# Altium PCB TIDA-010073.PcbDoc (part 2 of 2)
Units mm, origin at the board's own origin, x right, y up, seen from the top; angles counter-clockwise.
Board outline 68.14 x 25.33 mm, 2 copper layers (Top Layer, Bottom Layer), stack 1.575 mm thick; 47 components, 34 nets, 125 pads, 64 vias.
Unrouted connection lines stored in the file: 4.
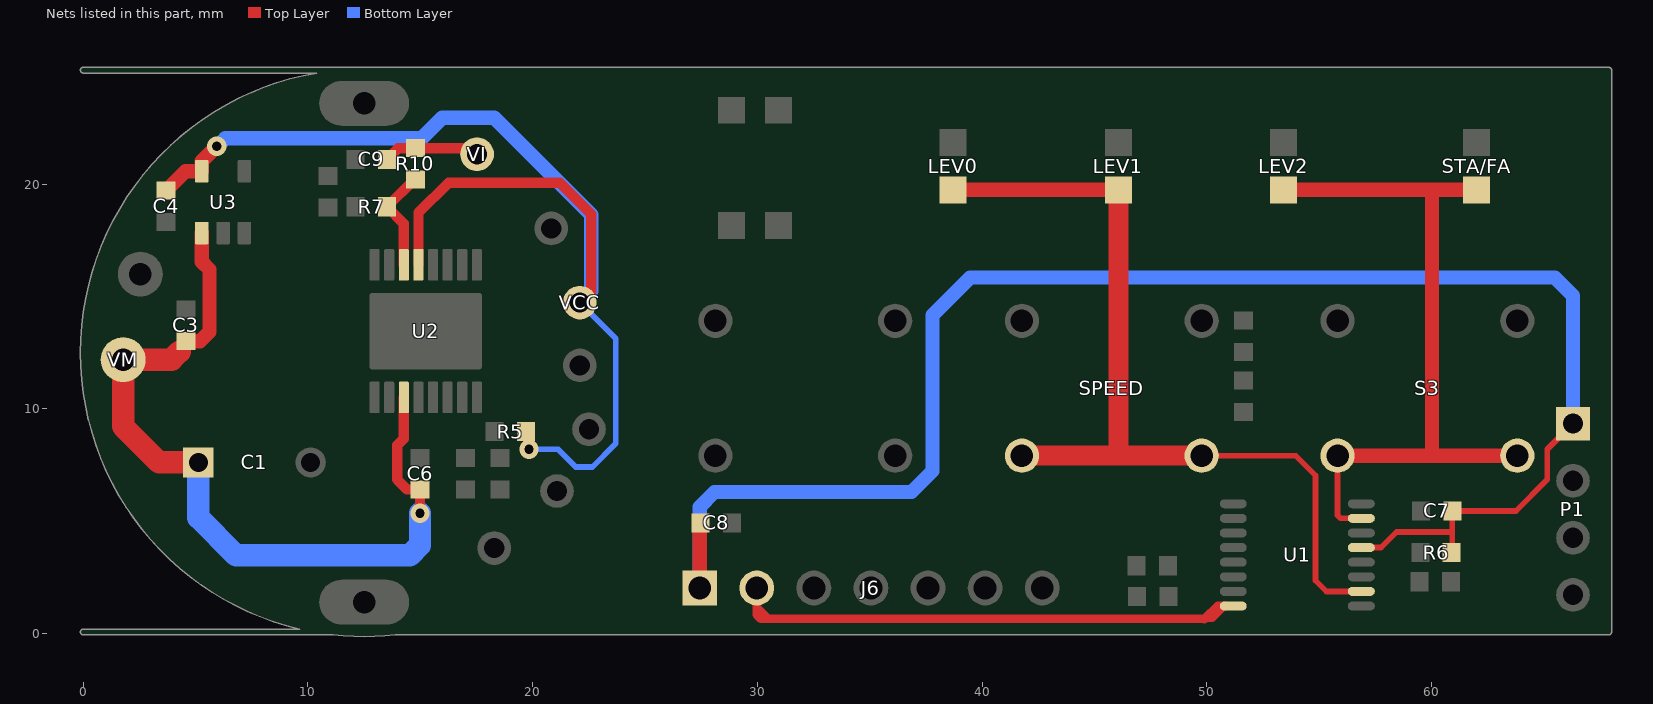
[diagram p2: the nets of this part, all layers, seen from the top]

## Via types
v1: diameter 0.508, hole 0.381, Top Layer to Bottom Layer, 28 vias
v2: diameter 0.864, hole 0.406, Top Layer to Bottom Layer, 19 vias
v3: diameter 0.5, hole 0.2, Top Layer to Bottom Layer, tented both sides, 12 vias
v4: diameter 0.5, hole 0.2, Top Layer to Bottom Layer, 3 vias
v5: diameter 0.508, hole 0.254, Top Layer to Bottom Layer, 2 vias

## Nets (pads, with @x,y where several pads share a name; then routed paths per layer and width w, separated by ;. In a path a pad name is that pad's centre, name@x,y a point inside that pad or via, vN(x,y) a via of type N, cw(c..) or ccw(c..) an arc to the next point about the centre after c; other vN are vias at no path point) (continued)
Seg1_MCU: LEV0.1 LEV1.1 SPEED.B SPEED.D U1.2 | length 39.5
  Top Layer w0.254: SPEED.D@49.771,7.922 53.952,7.922 54.839,7.036 54.839,2.362 55.321,1.88 U1.2@56.876,1.88
  Top Layer w0.635: LEV0.1@38.71,19.753 LEV1.1@46.063,19.753
  Top Layer w0.889: SPEED.B@41.771,7.922 46.076,7.922 ; LEV1.1@46.063,19.753 46.063,7.935 46.076,7.922 ; SPEED.D@49.771,7.922 46.076,7.922
Seg2_MCU: LEV2.1 S3.B S3.D STA/FA.1 U1.7 | length 32.2
  Top Layer w0.254: S3.B@55.817,7.922 55.817,5.27 55.957,5.13 U1.7@56.876,5.13
  Top Layer w0.635: LEV2.1@53.416,19.753 STA/FA.1@62.001,19.753 ; S3.B@55.817,7.922 60.02,7.922 ; 60.02,19.727 60.02,7.922 ; S3.D@63.817,7.922 60.02,7.922
V_IPROPI: R7.2 R10.1 U2.6 | length 4.7
  Top Layer w0.457: U2.6@14.265,16.412 14.265,18.25 R7.2@13.516,18.999 14.721,20.204 R10.1@14.783,20.204
V_IPROPI_Fil: C9.1 R10.2 VI.1 | length 4.3
  Top Layer w0.457: C9.1@13.513,21.107 14.01,21.604 R10.2@14.783,21.604 17.258,21.604 VI.1@17.526,21.336
V_IPROPI_MCU: J6.2 U1.16 | length 24.8
  Top Layer w0.254: J6.2@29.972,2.032 29.972,1.245 30.556,0.66 ; 49.886,0.635 50.256,0.635 50.851,1.23 U1.16@51.176,1.23
  Top Layer w0.381: 29.972,1.245 29.972,0.838 30.15,0.66 30.556,0.66 49.911,0.66 ; 49.886,0.635 49.911,0.66 ; U1.16@50.851,1.23 50.481,1.23 49.911,0.66
VCC: C4.1 R5.1 U2.5 U3.5 VCC.1 | length 54.1
  Top Layer w0.254: R5.1@19.699,8.992 19.699,8.342 v2(19.837,8.204)
  Top Layer w0.457: U2.5@14.915,16.412 14.915,18.725 16.256,20.066 21.212,20.066 22.606,18.672 22.606,15.24 VCC.1@22.098,14.732
  Top Layer w0.635: C4.1@3.683,19.713 4.547,20.577 U3.5@5.273,20.577 5.273,21.021 v2(5.944,21.692)
  Bottom Layer w0.254: v2(19.837,8.204) 21.133,8.204 21.92,7.417 22.657,7.417 23.698,8.458 23.698,13.132 VCC.1@22.098,14.732
  Bottom Layer w0.635: v2(5.944,21.692) 6.325,22.047 15.062,22.047 15.977,22.962 18.288,22.962 22.606,18.644 22.606,15.24 VCC.1@22.098,14.732
VCC1: C7.1 C8.1 J6.1 P1.1@66.294,9.347 R6.1 U1.5 | length 73.5
  Top Layer w0.254: U1.5@56.876,3.83 57.754,3.83 58.445,4.521 60.808,4.521 ; R6.1@60.898,3.607 60.923,3.632 C7.1@60.923,5.461 63.754,5.461 65.151,6.858 65.151,8.204 P1.1@66.294,9.347
  Top Layer w0.635: J6.1@27.432,2.032 27.432,4.891 C8.1@27.469,4.928
  Bottom Layer w0.635: J6.1@27.432,2.032 27.432,5.639 28.092,6.299 36.855,6.299 37.795,7.239 37.795,14.173 39.472,15.85 65.481,15.85 66.294,15.037 P1.1@66.294,9.347
VM: C1.1 C3.1 C6.1 U2.11 U3.1 VM.1 | length 36
  Top Layer w0.457: U2.11@14.265,10.512 14.265,8.677 13.97,8.382 13.97,6.858 14.416,6.412 C6.1@14.986,6.412 v2(14.986,5.359)
  Top Layer w0.635: C3.1@4.572,13.016 5.193,13.016 5.613,13.437 5.613,16.205 5.273,16.546 U3.1@5.273,17.827
  Top Layer w1: 4.293,12.548 3.937,12.192 VM.1@1.778,12.192 1.778,9.22 3.378,7.62 C1.1@5.12,7.62
  Bottom Layer w1: C1.1@5.12,7.62 5.12,5.167 6.807,3.48 14.529,3.48 14.986,3.937 v2(14.986,5.359)
pads on no net: LBL1.0 U1.8 U2.17@15.24,13.462 U3.3 U3.4

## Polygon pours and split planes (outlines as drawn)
GND1 on Bottom Layer "BOTTOM_LAYER_GND1_P000" (solid, remove dead copper, pour order 0): 25.885,25.076 25.885,0.076 67.885,0.076 67.885,25.076
GND on Bottom Layer "BOTTOM_LAYER_GND_P006" (solid, remove dead copper, pour order 6): 25.552,25.044 25.425,24.917 25.425,0.051 0.051,0.051 -0.025,0.127 -0.025,25.324
GND on Top Layer "TOP_LAYER_GND_P004" (solid, remove dead copper, pour order 4): -0.051,25.044 -0.025,25.019 -0.025,0.051 24.206,0.051 25.121,0.965 25.121,25.273 24.587,25.806
GND1 on Top Layer "TOP_LAYER_GND1_P002" (solid, remove dead copper, pour order 2): 25.885,25.07 25.885,0.076 67.885,0.076 67.885,25.076 67.841,25.121

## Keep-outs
Keep-Out Layer:
  circle w0.254: c12.5,12.5 r12.5
  lines w0.381: 25.885,25.07 25.885,0.076 25.961,0 67.809,0 67.885,0.076 67.885,25.076 67.841,25.121 25.93,25.121 25.885,25.076
  text ".Layer_Name" at 14.656,-21.806 h1.14

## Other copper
Top Layer:
  text ".Layer_Name" at 14.656,-21.806 h1.14
Bottom Layer:
  text ".Layer_Name" at 14.656,-21.806 h1.14

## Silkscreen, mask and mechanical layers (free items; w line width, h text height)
Top Overlay:
  text ".Layer_Name" at 14.656,-21.806 h1.14
Bottom Overlay:
  region: 12.421,6.198 4.801,6.198 4.801,3.658 12.421,3.658
  text "TIDA-010073.Rev.1" at 12.725,8.941 h1.14
  text "TIDA-010073.Rev.1" at 59.08,1.194 h1.14
  text ".Layer_Name" at 14.656,-21.806 h1.14
Top Paste:
  text ".Layer_Name" at 14.656,-21.806 h1.14
Bottom Paste:
  text ".Layer_Name" at 14.656,-21.806 h1.14
Top Solder:
  lines w0.381: 7.417,13.741 7.442,13.767 12.421,13.767 ; 7.696,15.85 9.068,14.478 12.294,14.478 ; 7.747,11.887 8.89,13.03 12.395,13.03 ; 8.052,10.693 9.601,12.243 12.446,12.243 ; 8.534,9.449 10.414,11.328 12.446,11.328
  text ".Layer_Name" at 14.656,-21.806 h1.14
  text ".Layer_Name" at 14.656,-21.806 h1.14
Bottom Solder:
  lines w0.381: 6.426,13.691 6.502,13.767 12.421,13.767 ; 6.985,18.952 7.133,18.952 11.608,14.478 12.294,14.478 ; 7.823,11.1 9.525,12.802 12.446,12.802 ; 8.534,9.449 11.048,11.962 12.69,11.962 ; 9.042,20.244 9.042,18.72 12.598,15.164 ; 10.414,8.992 12.573,11.151 12.598,11.151 ; 12.497,19.863 12.497,16.637 13.335,15.799 ; 13.52,7.638 13.52,11.278 13.52,11.575 ; 14.072,15.704 14.072,18.669 14.072,20.015 ; 14.511,7.662 14.529,7.68 14.529,11.405 ; 15.113,15.57 15.113,18.669 15.113,20.041 ; 15.443,11.557 15.443,7.68 15.461,7.662 ; 16.231,15.789 16.231,18.618 16.231,19.831 ; 16.383,7.874 16.383,11.506 ; 17.12,15.494 17.12,16.208 17.12,18.593 17.12,18.618 18.263,19.761 ; 17.399,7.918 17.399,11.532 ; 17.653,13.868 19.025,13.868 20.041,14.884 ; 17.678,15.011 18.44,15.011 19.761,16.332 ; 17.805,11.836 19.253,11.836 20.117,10.973 ; 17.805,12.802 19.761,12.802 20.422,13.462
  text ".Layer_Name" at 14.656,-21.806 h1.14
Drill Guide:
  text ".Layer_Name" at 14.656,-21.806 h1.14
M1 Board Outline:
  circle w0.254: c12.5,12.5 r12.5
  lines w0.254: 25.885,0.076 67.885,0.076 67.885,25.076 25.885,25.076 25.885,0.076
  text ".Layer_Name" at 14.656,-21.806 h1.14
M2 Board Dimensions:
  rectangle: 3.175,-10.16 12.7,-6.985
  rectangle: 0,-6.985 3.175,-3.81
  lines w0.178: 0,-6.985 25.4,-6.985 ; 3.175,-10.16 3.175,-3.81 ; 6.35,-10.16 6.35,-3.81 ; 12.7,-10.16 12.7,-3.81 ; 19.05,-10.16 19.05,-3.81 ; 0,-10.16 0,-3.81 25.4,-3.81 25.4,-10.16 0,-10.16
  text ".Layer_Name" at 14.656,-21.806 h1.14
M3 3D STEP Top:
  text ".Layer_Name" at 14.656,-21.806 h1.14
M4 3D STEP Bottom:
  text ".Layer_Name" at 14.656,-21.806 h1.14
M5 Assembly Top:
  lines w0.254: -7.417,-23.626 160.223,-23.626 ; -7.417,-18.462 160.274,-18.462 ; -7.417,-13.297 -7.417,-28.791 94.31,-28.791 160.274,-28.791 160.274,-13.297 -7.404,-13.297 -7.404,-28.791 32.614,-28.791 ; 55.194,-28.791 55.194,-13.297 ; 87.376,-18.462 87.376,-13.297 ; 108.712,-18.462 108.712,-13.297 ; 124.511,-28.956 124.511,-23.804
  text "COMPONENTS MARKED 'DNP' SHOULD NOT BE POPULATED." at 29.299,-8.09 h0.76
  text "ASSEMBLY VARIANT:" at 29.286,-11.024 h0.76
  text ".VariantName" at 55.601,-11.024 h0.76
  text "PCB VIEWED FROM TOP SIDE" at -5.804,-16.654 h1.14
  text "BOARD #:" at 57.099,-16.654 h1.14
  text ".PRJ_Number" at 70.955,-16.654 h1.14
  text "REV:" at 92.405,-16.654 h1.14
  text ".PCB_Rev" at 99.809,-16.654 h1.14
  text "SVN REV:" at 113.69,-16.654 h1.14
  text ".VersionControl_RevNumber" at 126.543,-16.654 h1.14
  text "TID #:" at 57.099,-21.819 h1.14
  text ".TID" at 70.955,-21.819 h1.14
  text "PLOT NAME =" at -5.804,-27.034 h1.14
  text ".plot_File_Name" at 14.656,-27.034 h1.14
  text "GENERATED    :" at 57.15,-27.034 h1.14
  text ".Print_Date" at 79.235,-27.034 h1.14
  text ".Print_Time" at 97.752,-27.034 h1.14
  text "TEXAS INSTRUMENTS" at 129.87,-27.034 h1.14
M6 Assembly Bottom:
  lines w0.254: -7.429,-18.474 160.261,-18.474 ; -7.379,-23.639 160.261,-23.639 ; 28.334,-28.969 28.334,-23.817 ; 44.133,-18.474 44.133,-13.31 ; 65.468,-18.474 65.468,-13.31 ; 97.65,-28.804 97.65,-13.31 ; 120.231,-28.804 160.249,-28.804 160.249,-13.31 -7.429,-13.31 -7.429,-28.804 58.534,-28.804 160.261,-28.804 160.261,-13.31
  text "COMPONENTS MARKED 'DNP' SHOULD NOT BE POPULATED." at 154.991,-8.077 h0.76
  text ".VariantName" at 128.473,-11.024 h0.76
  text "ASSEMBLY VARIANT:" at 154.864,-11.024 h0.76
  text ".VersionControl_RevNumber" at 26.302,-16.667 h1.14
  text "SVN REV:" at 39.154,-16.667 h1.14
  text ".PCB_Rev" at 53.035,-16.667 h1.14
  text "REV:" at 60.439,-16.667 h1.14
  text ".PRJ_Number" at 81.89,-16.667 h1.14
  text "BOARD #:" at 95.745,-16.667 h1.14
  text "PCB VIEWED FROM BOTTOM SIDE" at 158.648,-16.667 h1.14
  text ".TID" at 81.89,-21.831 h1.14
  text "TID #:" at 95.745,-21.831 h1.14
  text "TEXAS INSTRUMENTS" at 22.974,-27.047 h1.14
  text ".Print_Time" at 55.093,-27.047 h1.14
  text ".Print_Date" at 73.609,-27.047 h1.14
  text "GENERATED    :" at 95.694,-27.047 h1.14
  text ".plot_File_Name" at 138.189,-27.047 h1.14
  text "PLOT NAME =" at 158.648,-27.047 h1.14
M9 Title Sheet:
  drawing of 57 lines, arcs and shapes, not listed
  text "1" at 18.792,204.127 h1.14
  text "2" at 82.182,204.127 h1.14
  text "3" at 145.411,204.127 h1.14
  text "4" at 209.08,204.127 h1.14
  text "5" at 272.555,204.127 h1.14
  text "6" at 336.182,204.127 h1.14
  text "A" at -10.579,175.095 h1.14
  text "A" at 365.341,175.095 h1.14
  text "B" at -10.579,114.643 h1.14
  text "B" at 365.341,114.643 h1.14
  text "C" at -10.579,54.318 h1.14
  text "C" at 365.341,54.318 h1.14
  text "PROJECT TITLE:" at 288.125,7.048 h1.14
  text "18V_2A_25mm diameter brushed dc motor driver reference design" at 289.395,3.662 h1.14
  text "DESIGNED FOR:" at 288.125,-0.597 h1.14
  text "Public Release" at 289.395,-4.153 h1.14
  text "D" at -10.579,-5.88 h1.14
  text "D" at 365.341,-5.88 h1.14
  text "FILE NAME:" at 288.125,-8.217 h1.14
  text "TIDA-010073.PcbDoc" at 289.395,-11.265 h1.14
  text "Texas Instruments (TI) and/or its licensors do not warrant the accuracy or completeness of this specification" at 161.9,-15.376 h1.14
  text "ENGINEER:" at 288.125,-15.583 h1.14
  text "LAYOUT BY:" at 326.352,-15.583 h1.14
  text "or any information contained therein. TI and/or its licensors do not warrant that this design will meet" at 160.757,-18.237 h1.14
  text "Hawken Li" at 289.395,-19.52 h1.14
  text "Hawken Li" at 327.635,-19.52 h1.14
  text "the specifications, will be suitable for your application or fit for any particular purpose, or will operate in" at 160.757,-21.099 h1.14
  text ".Layer_Name" at 14.656,-21.806 h1.14
  text "ALTIUM DESIGNER VERSION:" at 326.352,-23.457 h1.14
  text "an implementation. TI and/or its licensors do not warrant that the design is production worthy. You should" at 160.757,-23.961 h1.14
  text "completely validate and test your design implementation to confirm the system functionality for your application." at 161.9,-26.822 h1.14
  text "Scale:1.00" at 289.395,-26.843 h1.14
  text "17.1.9 (Build 472)" at 327.635,-26.843 h1.14
  text "1" at 18.792,-32.093 h1.14
  text "2" at 82.182,-32.093 h1.14
  text "3" at 145.411,-32.093 h1.14
  text "4" at 209.08,-32.093 h1.14
  text "5" at 272.555,-32.093 h1.14
  text "6" at 336.182,-32.093 h1.14
M10 Fab Notes:
  drawing of 189 lines, arcs and shapes, not listed
  text "DESIGN INFORMATION" at 314.503,161.447 h1.14
  text "MIN. TRACK WIDTH:" at 298.131,158.091 h1.14
  text "8" at 325.976,158.091 h1.14
  text "MIL" at 329.907,158.091 h1.14
  text "MIN. CLEARANCE:" at 298.131,154.938 h1.14
  text "0.2" at 324.452,154.938 h1.14
  text "mm" at 329.907,154.938 h1.14
  text "MIN. VIA PAD SIZE:" at 298.131,151.785 h1.14
  text "24" at 325.214,151.785 h1.14
  text "MIL" at 329.907,151.785 h1.14
  text "0.05mm (2MIL)" at 315.784,148.486 h1.14
  text "MINIMUM ANNULAR RING" at 289.769,148.277 h1.14
  text "EXTERNAL" at 333.768,148.277 h1.14
  text "PER" at 294.849,145.48 h1.14
  text "IPC-D-275 CLASS 2 LEVEL C" at 300.437,145.48 h1.14
  text "MIL, HOLES" at 338.238,142.928 h1.14
  text "+/-" at 328.27,142.709 h1.14
  text "+/-" at 349.961,142.709 h1.14
  text "REGISTRATION TOLERANCES:" at 289.769,142.682 h1.14
  text "METAL" at 320.243,142.682 h1.14
  text "5" at 334.879,142.683 h1.14
  text "3" at 356.037,142.683 h1.14
  text "MIL" at 358.99,142.682 h1.14
  text "HOLE SIZE TOLERANCE (UNLESS OTHERWISE SPECIFIED):" at 289.769,140.185 h1.14
  text "+/-" at 349.961,140.112 h1.14
  text "3" at 356.037,140.085 h1.14
  text "MIL" at 358.99,140.085 h1.14
  text "MATERIAL:" at 287.87,136.589 h1.14
  text "FR-4 High Tg" at 312.926,133.324 h1.14
  text "X" at 309.257,133.122 h1.14
  text "FR-408" at 298.563,133.007 h1.14
  text "OTHER" at 336.358,133.007 h1.14
  text "62 MIL (1.6mm) +/-10%" at 306.694,129.374 h1.14
  text "X" at 303.643,129.312 h1.14
  text "THICKNESS:" at 289.769,129.165 h1.14
  text "OTHER" at 339.33,129.165 h1.14
  text "TOLERANCE:" at 289.769,125.652 h1.14
  text "X" at 311.314,125.652 h1.14
  text "ANSI IPC-6012 TYPE 3 CLASS 2" at 315.836,125.652 h1.14
  text "OTHER +/-" at 315.835,121.989 h1.14
  text "BOW & TWIST:" at 289.769,118.302 h1.14
  text "X" at 311.314,118.302 h1.14
  text "ANSI IPC-6012 TYPE 3 CLASS 2" at 315.836,118.302 h1.14
  text "OTHER +/-" at 315.835,114.576 h1.14
  text "DRILLING:" at 287.87,111.258 h1.14
  text "NC_DRILL FILES" at 332.599,108.586 h1.14
  text "REFERENCE:" at 289.769,108.486 h1.14
  text "X" at 306.463,108.484 h1.14
  text "AS SHOWN" at 310.984,108.486 h1.14
  text "X" at 329.348,108.486 h1.14
  text "OTHER" at 340.168,104.873 h1.14
  text "PTH COPPER THICKNESS:" at 289.761,104.783 h1.14
  text "X" at 318.697,104.783 h1.14
  text "20-30 um" at 321.948,104.783 h1.14
  text "BOARD FINISH:" at 287.87,101.034 h1.14
  text "SILKSCREEN:" at 291.812,98.237 h1.14
  text "X" at 316.14,98.237 h1.14
  text "TOP" at 319.112,98.237 h1.14
  text "X" at 329.094,98.237 h1.14
  text "BOTTOM" at 332.091,98.237 h1.14
  text "SILKSCREEN COLOR:" at 291.812,94.295 h1.14
  text "X" at 316.115,94.295 h1.14
  text "WHITE" at 319.112,94.295 h1.14
  text "OTHER" at 332.091,94.295 h1.14
  text "X" at 319.442,90.652 h1.14
  text "GREEN" at 322.439,90.652 h1.14
  text "OTHER" at 338.136,90.652 h1.14
  text "SOLDER RESIST COLOR:" at 291.812,90.477 h1.14
  text "X" at 319.442,86.734 h1.14
  text "MATTE" at 322.439,86.734 h1.14
  text "SEMI-GLOSS" at 338.125,86.717 h1.14
  text "IMMERSION GOLD (ENIG)" at 314.819,82.345 h1.14
  text "ENEPIG" at 348.793,82.162 h1.14
  text "SURFACE FINISH:" at 287.87,82.136 h1.14
  text "X" at 310.298,82.136 h1.14
  text "IMM. TIN/SILVER OR EQUIV" at 296.24,78.649 h1.14
  text "OTHER" at 332.599,78.549 h1.14
  text "ARRAY/PANEL:" at 287.87,74.602 h1.14
  text "CUT AND TRIM PER M1 BOARD OUTLINE" at 314.819,74.393 h1.14
  text "N.C. ROUTE" at 314.819,70.94 h1.14
  text "X" at 332.295,70.94 h1.14
  text "V. SCORE" at 336.816,70.94 h1.14
  text "CERTIFICATION:" at 287.87,67.66 h1.14
  text "MATERIALS AND WORKMANSHIP FOR ALL PCBS" at 306.285,67.66 h1.14
  text "TO MEET OR EXCEED THE REQUIREMENTS OF:" at 306.285,65.271 h1.14
  text "X" at 297.078,62.003 h1.14
  text "ANSI IPC-A-600F CLASS ->" at 300.329,62.003 h1.14
  text "X" at 342.188,62.003 h1.14
  text "2" at 344.982,62.003 h1.14
  text "1" at 336.981,61.965 h1.14
  text "3" at 353.973,61.965 h1.14
  text "X" at 317.702,58.252 h1.14
  text "RoHS" at 320.953,58.252 h1.14
  text "OTHER" at 337.321,58.252 h1.14
  text "PER ORDER" at 347.407,58.252 h1.14
  text "ALL BOARDS MUST MEET OR EXCEED UL94-V0 REQUIREMENTS." at 288.569,54.345 h1.14
  text "PCB MUST BEAR THE UL94V-0 UL REGISTERED MATERIAL ID NUMBER" at 288.569,51.397 h1.14
  text "ADDITIONAL REQUIREMENTS:" at 287.87,47.094 h1.14
  text "MICROSECTION:" at 289.769,44.373 h1.14
  text "YES" at 312.775,44.373 h1.14
  text "REQUIRED" at 334.657,40.707 h1.14
  text "BARE BOARD ELEC. TEST:" at 289.769,40.634 h1.14
  text "NONE" at 322.935,40.634 h1.14
  text "X" at 331.66,40.634 h1.14
  text "PER ORDER" at 349.693,40.634 h1.14
  text "XX MIL VIAS REQUIRE NON-CONDUCTIVE FILL AND PLANARIZE" at 294.04,35.428 h1.14
  text "XX MIL VIAS REQUIRE CONDUCTIVE FILL AND PLANARIZE" at 294.243,32.787 h1.14
  text "OUTER XX MIL TRACES REQUIRE 50 OHM SINGLE-ENDED IMPEDANCE" at 294.218,28.637 h1.14
  text "LAYER 2 & 3 (INNER LAYERS) XX MIL WIDE, XX MIL SPACE / TRACES REQUIRE 100 OHM DIFFERENTIAL IMPEDANCE" at 294.015,22.65 h1.14
  text ".Layer_Name" at 14.656,-21.806 h1.14
M11 Gerber Information:
  lines w0.254: -7.417,-23.626 160.223,-23.626 ; -7.417,-18.462 160.274,-18.462 ; -7.417,-13.297 -7.417,-28.791 94.31,-28.791 160.274,-28.791 160.274,-13.297 -7.404,-13.297 -7.404,-28.791 32.614,-28.791 ; 55.194,-28.791 55.194,-13.297 ; 87.376,-18.462 87.376,-13.297 ; 108.712,-18.462 108.712,-13.297 ; 124.511,-28.956 124.511,-23.804
  text "ALL ARTWORK VIEWED FROM TOP SIDE" at -5.804,-16.654 h1.14
  text "BOARD #:" at 57.099,-16.654 h1.14
  text ".PRJ_Number" at 70.955,-16.654 h1.14
  text "REV:" at 92.405,-16.654 h1.14
  text ".PCB_Rev" at 99.809,-16.654 h1.14
  text "SVN REV:" at 113.69,-16.654 h1.14
  text ".VersionControl_RevNumber" at 126.543,-16.654 h1.14
  text "LAYER NAME =" at -5.804,-21.806 h1.14
  text "TID #:" at 57.099,-21.819 h1.14
  text ".TID" at 70.955,-21.819 h1.14
  text "PLOT NAME =" at -5.804,-27.034 h1.14
  text ".plot_File_Name" at 14.656,-27.034 h1.14
  text "GENERATED    :" at 57.15,-27.034 h1.14
  text ".Print_Date" at 79.235,-27.034 h1.14
  text ".Print_Time" at 97.752,-27.034 h1.14
  text "TEXAS INSTRUMENTS" at 129.87,-27.034 h1.14
M12 Stackup:
  drawing of 191 lines, arcs and shapes, not listed
  text "Layer" at 248.484,199.644 h1.14
  text "Name" at 256.166,199.644 h1.14
  text "Material" at 273.751,199.644 h1.14
  text "Thickness" at 290.002,199.644 h1.14
  text "Constant" at 302.255,199.644 h1.14
  text "Board Layer Stack" at 312.984,199.644 h1.14
  text "1" at 248.484,197.358 h1.14
  text "Top Overlay" at 256.166,197.358 h1.14
  text "2" at 248.484,195.072 h1.14
  text "Top Solder" at 256.166,195.072 h1.14
  text "Solder Resist" at 273.751,195.072 h1.14
  text "0.40mil" at 290.002,195.072 h1.14
  text "3.5" at 302.255,195.072 h1.14
  text "3" at 248.484,192.786 h1.14
  text "Top Layer" at 256.166,192.786 h1.14
  text "Copper" at 273.751,192.786 h1.14
  text "1.40mil" at 290.002,192.786 h1.14
  text "4" at 248.484,190.5 h1.14
  text "Dielectric1" at 256.166,190.5 h1.14
  text "FR-4" at 273.751,190.5 h1.14
  text "59.20mil" at 290.002,190.5 h1.14
  text "4.8" at 302.255,190.5 h1.14
  text "5" at 248.484,188.214 h1.14
  text "Bottom Layer" at 256.166,188.214 h1.14
  text "Copper" at 273.751,188.214 h1.14
  text "1.40mil" at 290.002,188.214 h1.14
  text "6" at 248.484,185.928 h1.14
  text "Bottom Solder" at 256.166,185.928 h1.14
  text "Solder Resist" at 273.751,185.928 h1.14
  text "0.40mil" at 290.002,185.928 h1.14
  text "3.5" at 302.255,185.928 h1.14
  text "7" at 248.484,183.642 h1.14
  text "Bottom Overlay" at 256.166,183.642 h1.14
  text ".Layer_Name" at 14.656,-21.806 h1.14
M13 Component Bodies Top:
  text ".Layer_Name" at 14.656,-21.806 h1.14
M14 Component Bodies Bottom:
  text ".Layer_Name" at 14.656,-21.806 h1.14
M15 Courtyards Top:
  text ".Layer_Name" at 14.656,-21.806 h1.14
M16 Courtyards Bottom:
  text ".Layer_Name" at 14.656,-21.806 h1.14
Drill Drawing:
  circle w0.127: c135.442,69.717 r0.421
  lines w0.127: 135.021,72.035 135.864,72.035 135.442,71.192 135.021,72.035 ; 135.021,73.3 135.231,73.3 135.442,73.089 135.653,73.3 135.864,73.3 135.653,73.51 135.864,73.721 135.653,73.721 135.442,73.932 135.231,73.721 135.021,73.721 135.231,73.51 135.021,73.3 ; 135.021,74.985 135.442,75.196 135.864,74.985 135.653,75.407 135.864,75.828 135.442,75.618 135.021,75.828 135.231,75.407 135.021,74.985 ; 135.021,76.882 135.864,76.882 135.864,77.725 135.021,77.725 135.021,76.882 ; 135.021,78.779 135.021,78.99 135.231,79.2 135.021,79.411 135.021,79.622 135.231,79.622 135.442,79.411 135.653,79.622 135.864,79.622 135.864,79.411 135.653,79.2 135.864,78.99 135.864,78.779 135.653,78.779 135.442,78.99 135.231,78.779 135.021,78.779 ; 135.021,80.675 135.864,80.675 135.864,81.518 135.021,81.518 135.021,80.675 ; 135.021,82.994 135.442,82.572 135.864,82.994 135.442,83.415 135.021,82.994 ; 135.021,84.68 135.231,84.68 135.231,84.469 135.653,84.469 135.653,84.68 135.864,84.68 135.864,85.101 135.653,85.101 135.653,85.312 135.231,85.312 135.231,85.101 135.021,85.101 135.021,84.68 ; 135.189,80.844 135.695,80.844 135.695,81.35 135.189,81.35 135.189,80.844
  lines w0.305: 134.264,68.726 193.591,68.726 ; 134.264,85.796 193.591,85.796 ; 140.281,66.83 140.281,87.693 ; 146.327,66.83 146.327,87.693 ; 158.181,66.83 158.181,87.693 ; 162.838,66.83 162.838,87.693 ; 169.708,66.83 169.708,87.693 ; 183.216,66.83 183.216,87.693 ; 134.264,66.83 193.591,66.83 193.591,87.693 134.264,87.693 134.264,66.83
  text "Symbol" at 135.402,86.365 h1.37
  text "Quantity" at 140.85,86.365 h1.37
  text "Finished Hole Size" at 146.896,86.365 h1.37
  text "Plated" at 158.75,86.365 h1.37
  text "Hole Type" at 163.407,86.365 h1.37
  text "Drill Layer Pair" at 170.277,86.365 h1.37
  text "Hole Tolerance" at 183.785,86.365 h1.37
  text "15" at 140.85,84.469 h1.14
  text "7.87mil (0.200mm)" at 146.896,84.469 h1.14
  text "PTH" at 158.75,84.469 h1.14
  text "Round" at 163.407,84.469 h1.14
  text "Top Layer - Bottom Layer" at 170.277,84.469 h1.14
  text "2" at 140.85,82.572 h1.14
  text "10.00mil (0.254mm)" at 146.896,82.572 h1.14
  text "PTH" at 158.75,82.572 h1.14
  text "Round" at 163.407,82.572 h1.14
  text "Top Layer - Bottom Layer" at 170.277,82.572 h1.14
  text "28" at 140.85,80.675 h1.14
  text "15.00mil (0.381mm)" at 146.896,80.675 h1.14
  text "PTH" at 158.75,80.675 h1.14
  text "Round" at 163.407,80.675 h1.14
  text "Top Layer - Bottom Layer" at 170.277,80.675 h1.14
  text "19" at 140.85,78.779 h1.14
  text "16.00mil (0.406mm)" at 146.896,78.779 h1.14
  text "PTH" at 158.75,78.779 h1.14
  text "Round" at 163.407,78.779 h1.14
  text "Top Layer - Bottom Layer" at 170.277,78.779 h1.14
  text "2" at 140.85,76.882 h1.14
  text "33.47mil (0.850mm)" at 146.896,76.882 h1.14
  text "PTH" at 158.75,76.882 h1.14
  text "Round" at 163.407,76.882 h1.14
  text "Top Layer - Bottom Layer" at 170.277,76.882 h1.14
  text "11" at 140.85,74.985 h1.14
  text "35.43mil (0.900mm)" at 146.896,74.985 h1.14
  text "PTH" at 158.75,74.985 h1.14
  text "Round" at 163.407,74.985 h1.14
  text "Top Layer - Bottom Layer" at 170.277,74.985 h1.14
  text "14" at 140.85,73.089 h1.14
  text "39.37mil (1.000mm)" at 146.896,73.089 h1.14
  text "PTH" at 158.75,73.089 h1.14
  text "Round" at 163.407,73.089 h1.14
  text "Top Layer - Bottom Layer" at 170.277,73.089 h1.14
  text "7" at 140.85,71.192 h1.14
  text "40.00mil (1.016mm)" at 146.896,71.192 h1.14
  text "PTH" at 158.75,71.192 h1.14
  text "Round" at 163.407,71.192 h1.14
  text "Top Layer - Bottom Layer" at 170.277,71.192 h1.14
  text "2" at 140.85,69.295 h1.14
  text "39.37mil (1.000mm)" at 146.896,69.295 h1.14
  text "PTH" at 158.75,69.295 h1.14
  text "Slot" at 163.407,69.295 h1.14
  text "Top Layer - Bottom Layer" at 170.277,69.295 h1.14
  text "100 Total" at 140.85,67.399 h1.14
  text "Slot definitions :" at 135.402,65.883 h1.14
  text "Routed Path Length" at 143.842,65.883 h1.14
  text "= Calculated from tool start centre position to tool end centre position." at 153.977,65.883 h1.14
  text "Hole Length" at 143.842,64.936 h1.14
  text "= Routed Path Length + Tool Size = Slot length as defined in the PCB layout" at 150.173,64.936 h1.14
  text ".Layer_Name" at 14.656,-21.806 h1.14
M17 Embedded Cavity:
  text ".Layer_Name" at 14.656,-21.806 h1.14
M18 Embedded Assembly:
  text ".Layer_Name" at 14.656,-21.806 h1.14
M19 Embedded Keepout:
  text ".Layer_Name" at 14.656,-21.806 h1.14

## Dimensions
25.885,0.076 to 67.885,0.076 on M2 Board Dimensions
0,0 to 12.5,25 on M2 Board Dimensions
0,-10.16 to 25.4,-10.16 on M2 Board Dimensions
